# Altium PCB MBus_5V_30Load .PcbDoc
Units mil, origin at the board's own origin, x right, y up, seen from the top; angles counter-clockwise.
Board outline 2910 x 1732.28 mil, 2 copper layers (Top Layer, Bottom Layer); 54 components, 31 nets, 150 pads, 37 vias.
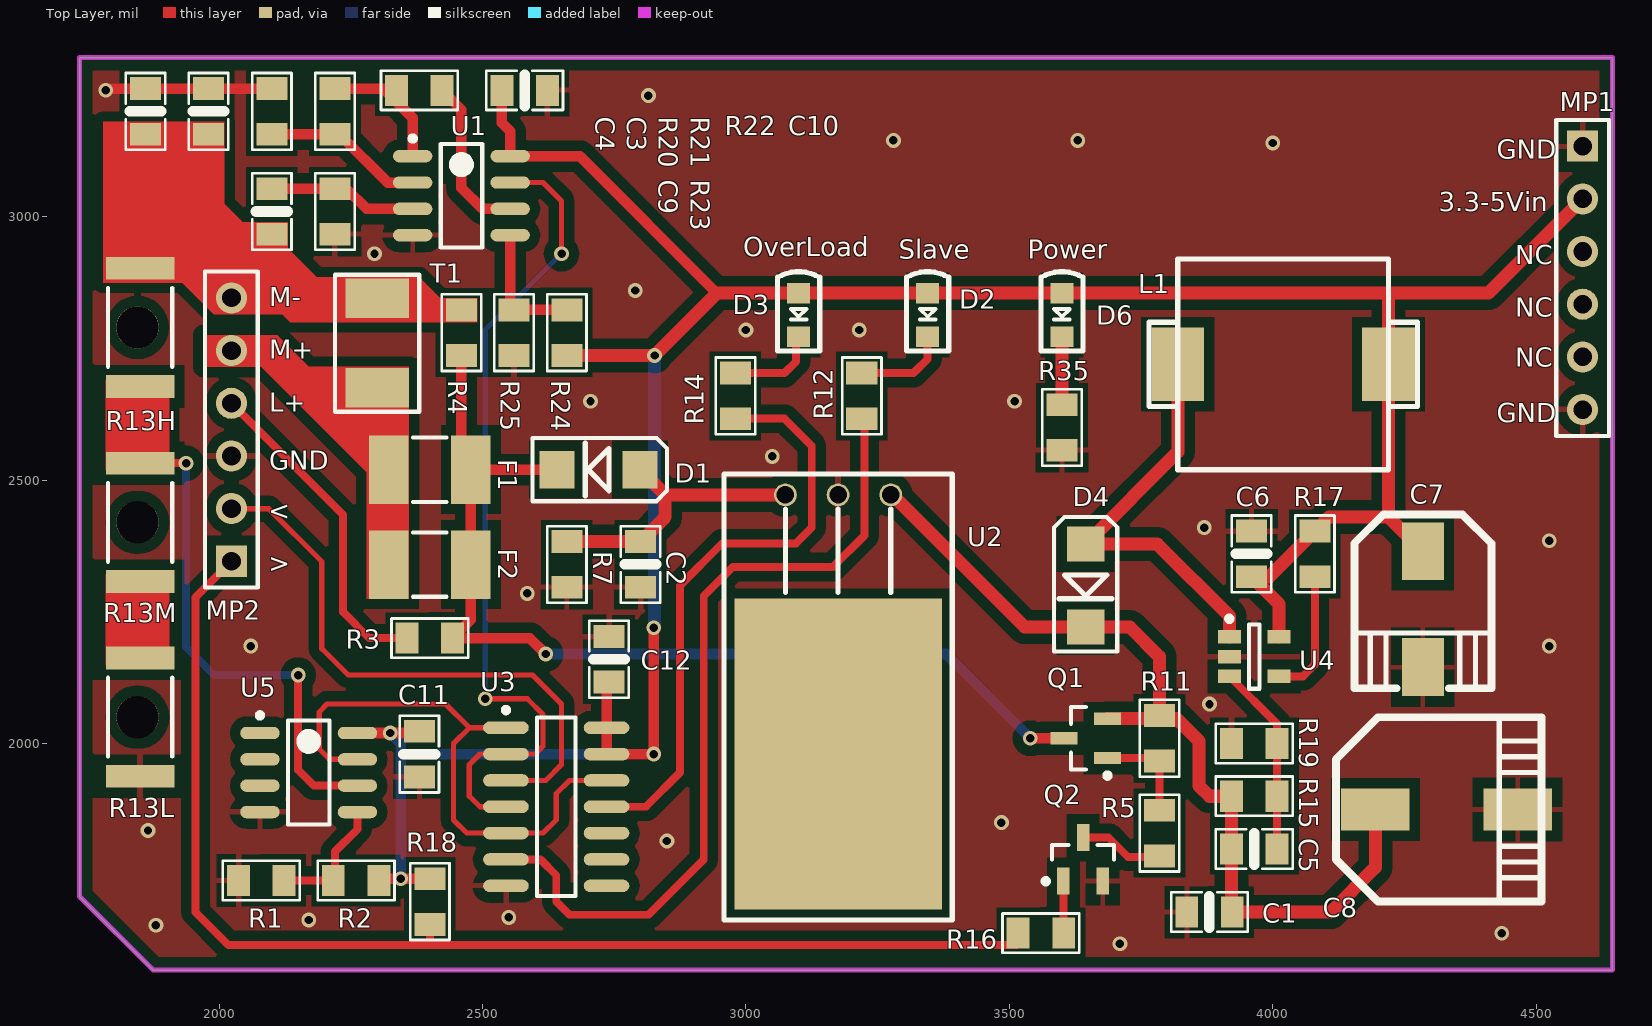
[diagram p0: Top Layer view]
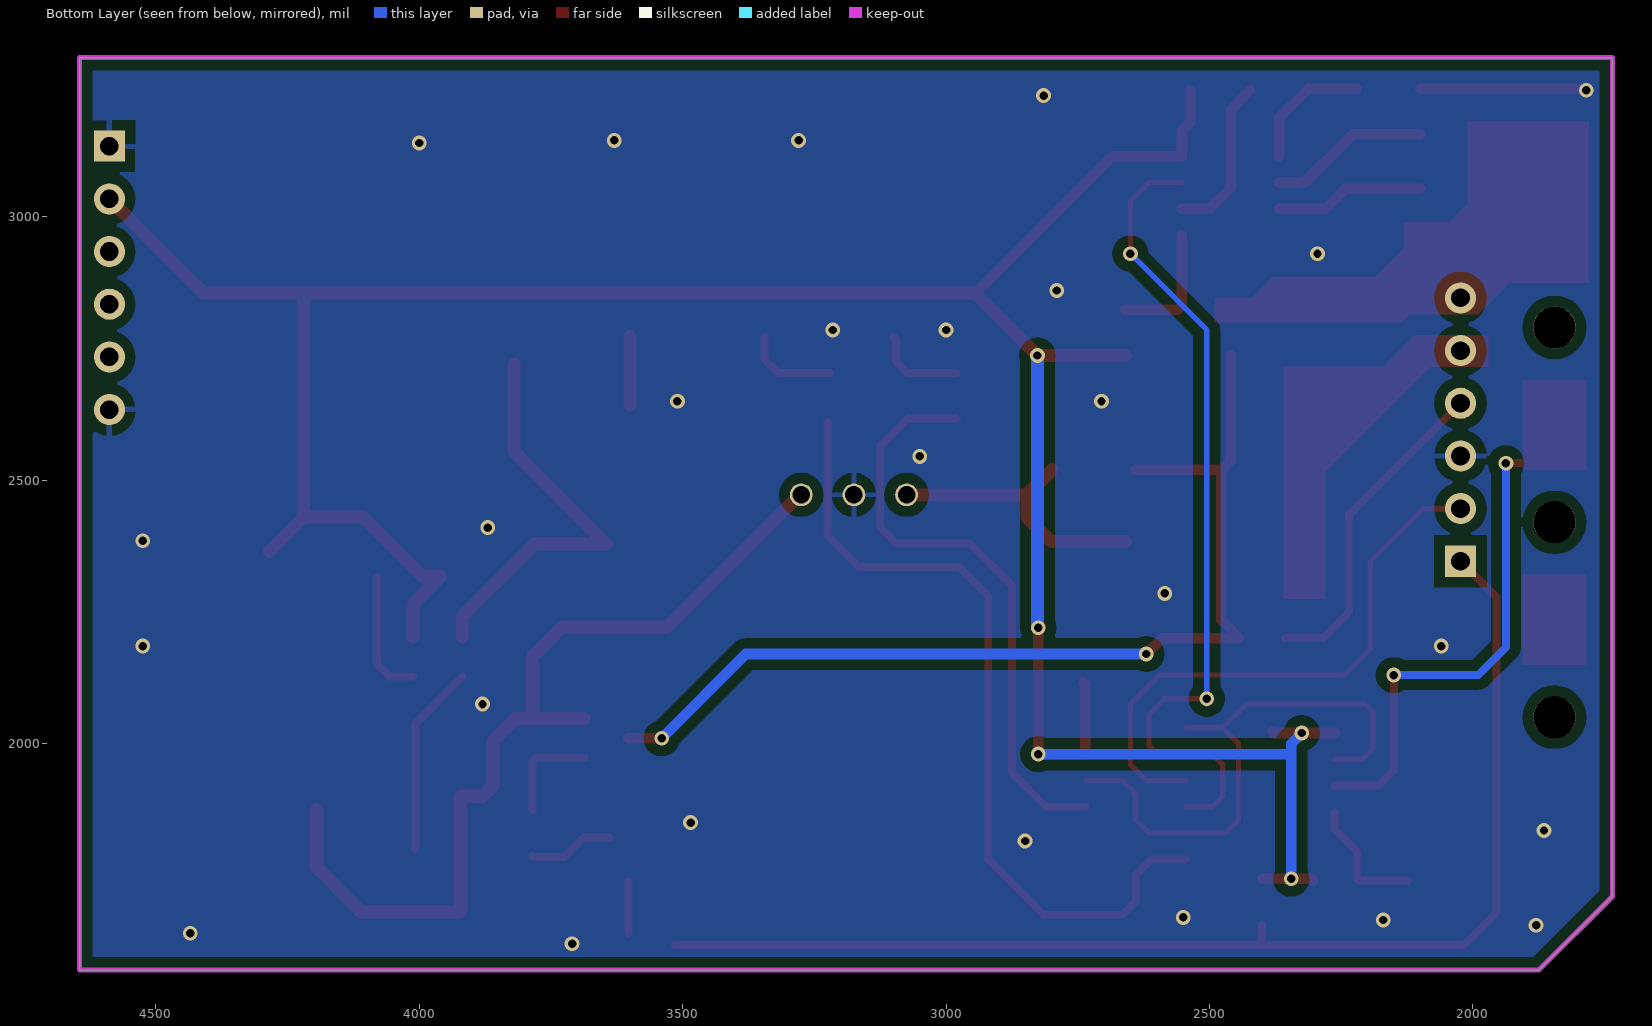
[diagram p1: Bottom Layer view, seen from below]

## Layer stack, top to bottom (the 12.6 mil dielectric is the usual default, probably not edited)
Top Layer: signal copper 1.4
Dielectric: dielectric 12.6, FR-4, Dk 4.8
Bottom Layer: signal copper 1.4

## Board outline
1875,1570 4645,1570 4645,3302.28 1735,3302.28 1735,1710

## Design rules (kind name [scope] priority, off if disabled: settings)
Clearance Clearance_1 [All vs InPolygon] p1: gap=20
Clearance [All] p2: gap=9
MinimumSolderMaskSliver [All] p1: minsoldermaskwidth=0
PlaneClearance [All] p1: clearance=10
PolygonConnect PolygonConnect_1 [IsVia] p1: connectstyle=Direct reliefconductorwidth=10 reliefentries=4 polygonreliefangle="90 Angle"
PolygonConnect [All] p2: connectstyle=Relief reliefconductorwidth=10 reliefentries=4 polygonreliefangle="90 Angle"
RoomDefinition MBus_5V_80Load [InComponentClass('MBus_5V_80Load')] p1: confinementstyle=ConfineIn formatcopy=TRUE lockcomponents=FALSE outline 1085,360 5900,360 5900,3530 1085,3530
RoutingVias [All] p1: holewidth=16 width=28 viastyle="Through Hole" minholewidth=14 minwidth=24 maxholewidth=30 maxwidth=50
SilkToSilkClearance [All] p1: silktosilkclearance=0
SilkscreenOverComponentPads [All] p1: minsilkscreentomaskgap=0
SolderMaskExpansion [All] p1: expansion=4
Width [All] p1: maxlimit=50 minlimit=10 preferedwidth=10 minimp=50.000000 maximp=50.000000 favimp=50.000000
24 further rules are at their usual default settings.

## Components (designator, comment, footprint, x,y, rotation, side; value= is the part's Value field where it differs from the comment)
C1 "0.1uF/50V X7R" 电容器0805 3880,1680 r0 top
C2 "0.1uF/50V X7R" 电容器0805 2800,2340 r90 top
C3 "0.1uF/50V" 电容器0805 1980,3200 r90 top
C4 "1nF/50V" 电容器0805 1860,3200 r90 top
C5 "82pF" 电容器0805 3965,1800 r180 top
C6 "0.1uF/50V" 电容器0805 3960,2360 r90 top
C7 "220uF/16V" 贴片电解电容-8mm 4285,2255 r90 top
C8 "100uF/50V" 贴片电解电容-10mm 4330,1875 r180 top
C9 "10uF/25V" 电容器0805 2100,3010 r270 top
C10 "0.1uF/50V" 电容器0805 2580,3240 r0 top
C11 "0.1uF/50V" 电容器0805 2380,1980 r270 top
C12 "0.1uF/50V" 电容器0805 2740,2160 r90 top
D1 "M7" DO-214AC 2720,2520 r0 top
D2 "MBUS" 0805-LED 3345,2855 r90 top
D3 "OVER" 0805-LED 3100,2855 r90 top
D4 "SS34" DO-214AC 3645,2300 r90 top
D6 "PWR" 0805-LED 3600,2855 r90 top
F1 "自恢复保险丝" PTC1812 2400,2520 r0 top
F2 "自恢复保险丝" PTC1812 2400,2340 r0 top
L1 "33uH" 贴片电感-10mm 4020,2720 r180 top
MP1 "Header 6" HDR1X6 4588.35,3133.98 r270 top locked
MP2 "Header 6" HDR1X6 2023.35,2345.98 r90 top locked
Q1 "FDN5618P" SOT23_N 3645,2010 r180 top
Q2 "S9014" SOT23_N 3640,1780 r90 top
R1 "10K" 电阻器0805 2080,1740 r0 top
R2 "100K(1%)" 电阻器0805 2260,1740 r180 top
R3 "10K" 电阻器0805 2400,2200 r0 top
R4 "270K" 电阻器0805 2460,2780 r90 top
R5 "27K" 电阻器0805 3785,1830 r270 top
R7 "10K" 电阻器0805 2660,2340 r90 top
R11 "10K" 电阻器0805 3785,2010 r90 top
R12 "10K" 电阻器0805 3220,2660 r90 top
R13H "1" RESC6332L 1850,2790 r270 top
R13L "2" RESC6332L 1850,2050 r270 top
R13M "2" RESC6332L 1850,2420 r270 top
R14 "10K" 电阻器0805 2980,2660 r90 top
R15 "285K" 电阻器0805 3965,1900 r180 top
R16 "10K" 电阻器0805 3560,1640 r0 top
R17 "47K" 电阻器0805 4080,2360 r270 top
R18 "100K" 电阻器0805 2400,1700 r90 top
R19 "13K3" 电阻器0805 3965,2000 r0 top
R20 "10K" 电阻器0805 2100,3200 r270 top
R21 "100K(1%)" 电阻器0805 2220,3200 r90 top
R22 "10K" 电阻器0805 2380,3240 r0 top
R23 "270K" 电阻器0805 2220,3010 r270 top
R24 "100K(1%)" 电阻器0805 2660,2780 r90 top
R25 "13K7" 电阻器0805 2560,2780 r90 top
R35 "10K" 电阻器0805 3600,2600 r90 top
T1 "SMBJ43CA" TVS(贴) 2300,2760 r270 top
U1 "LM358D" D008_L 2460,3040 r0 top
U2 "L7818CV" TO-220-3 3175,1980 r180 top
U3 "74HC08" SOP14 2640,1880 r0 top
U4 "LM2733YMF" MF05A_N 3965,2165 r0 top
U5 "LM358D" D008_L 2170,1945 r0 top

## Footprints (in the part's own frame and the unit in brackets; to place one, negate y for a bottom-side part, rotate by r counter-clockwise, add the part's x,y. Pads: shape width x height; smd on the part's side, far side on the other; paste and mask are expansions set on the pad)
0805-LED [mm]
  rect 1x1.1 smd: 1(0,0) 2(-2.1,0)
  silkscreen extent -2.79,-1.02 1.03,1.02
D008_L [mm] "SOIC, 8-Leads, Body 4.9x3.9mm, Pitch 1.27mm, IPC High Density"
  oval 1.9x0.6 smd: 1(-2.35,1.905) 2(-2.35,0.635) 3(-2.35,-0.635) 4(-2.35,-1.905) 5(2.35,-1.905) 6(2.35,-0.635) 7(2.35,0.635) 8(2.35,1.905)
  silkscreen extent -2.47,-2.5 1,2.88, body extent -2,-2.5 2,2.5, height 1.75
DO-214AC [mm]
  rect 1.7x1.8 smd: 1(2,0) 2(-2,0)
  silkscreen extent -3.17,-1.52 3.3,1.52
HDR1X6 [mm] "Connector; Header; 6 Position"
  rect 1.5x1.5 hole 0.9: 1(0,0)
  round 1.5 hole 0.9: 2(2.54,0) 3(5.08,0) 4(7.62,0) 5(10.16,0) 6(12.7,0)
  silkscreen extent -1.27,-1.27 13.97,1.27
MF05A_N [mm] "SOT23, 5-Leads, Body 2.9x1.6mm, Pitch 0.95mm, Lead Span 2.8mm, IPC Medium Density"
  rect 1.1x0.65 smd: 1(-1.2,0.95) 2(-1.2,0) 3(-1.2,-0.95) 4(1.2,-0.95) 5(1.2,0.95)
  silkscreen extent -1.32,-1.55 0.25,1.95, body extent -0.9,-1.55 0.9,1.55, height 1.19
PTC1812 [mm]
  rect 1.905x3.3 smd: 1(1.981,-0.005)
  rect 1.908x3.3 smd: 2(-1.981,-0.005)
  silkscreen extent -0.81,-1.56 0.79,1.55, body extent -2.41,-1.71 2.39,1.69, height 1.4
RESC6332L [mm] "Chip Resistor, Body 6.3x3.2mm, IPC High Density"
  rect 1.1x3.3 smd: 1(-2.85,0) 2(2.85,0)
  silkscreen extent -1.9,-1.55 1.9,1.55, body extent -3.22,-1.68 3.22,1.68, height 0.9
SOP14 [mm] "74HCxx"
  oval 2.2x0.6 smd: 1(-2.425,3.81) 2(-2.425,2.54) 3(-2.425,1.27) 4(-2.425,0) 5(-2.425,-1.27) 6(-2.425,-2.54) 7(-2.425,-3.81) 8(2.425,-3.81) 9(2.425,-2.54) 10(2.425,-1.27) 11(2.425,0) 12(2.425,1.27) 13(2.425,2.54) 14(2.425,3.81)
  silkscreen extent -2.55,-4.3 0.93,4.78, body extent -2,-4.28 2,4.28, height 1.75
SOT23_N [mm] "SOT23, 3-Leads, Body 2.9x1.3mm, Pitch 0.95mm, Lead Span 2.3mm, IPC Medium Density"
  rect 1.3x0.6 smd: 1(-1.05,0.95) 2(-1.05,-0.95) 3(1.05,0)
  silkscreen extent -1.18,-1.5 0.7,1.92, body extent -0.7,-1.5 0.7,1.5, height 1.1
TO-220-3 [mm]
  round 1.1 hole 0.85: 1(-2.54,-12.5) 2(0,-12.5) 3(2.54,-12.5)
  rect 10x15 smd: ""(0,0)
  silkscreen extent -5.5,-13.5 5.5,8
TVS(贴) [mil]
  rect 75x120 smd: 1(-85,0) 2(85,0)
  silkscreen extent -130,-80 130,80
电容器0805 [mm]
  rect 1.1x1.5 smd: 1(-1.1,0) 2(1.1,0)
  silkscreen extent -1.85,-0.95 1.85,0.95
电阻器0805 [mm]
  rect 1.1x1.5 smd: 1(-1.1,0) 2(1.1,0)
  silkscreen extent -1.85,-0.95 1.85,0.95
贴片电感-10mm [mil]
  rect 100x140 smd: 1(-200,0) 2(200,0)
  silkscreen extent -255,-200 255,200
贴片电解电容-8mm [mil]
  rect 110x80 smd: 1(110,0) 2(-110,0)
  silkscreen extent -150,-130 180,130
贴片电解电容-10mm [mil]
  rect 130x80 smd: 1(135,0) 2(-135,0)
  silkscreen extent -180,-175 210,175

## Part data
C1 C2 C3 C4 C5 C9: library part Cap, "Capacitor"
C6 C10 C11 C12: library part CAP2, "Capacitor"
C7 C8: library part "Cap Pol1", "Polarized Capacitor (Radial)"
D1: library part "Diode 1N4007", "High Conductance Fast Diode"
D2 D3 D6: library part LED2, "Typical RED, GREEN, YELLOW, AMBER GaAs LED"
D4: library part "D Schottky", "Schottky Diode"
F1 F2: library part "Fuse 1", "Fuse"
L1: library part "Inductor Iron", "Magnetic-Core Inductor"
MP1 MP2: "Header, 6-Pin"
Q1: library part MOSFET-P, "P-Channel MOSFET"
Q2: library part NPN, "NPN Bipolar Transistor"
R1 R2 R3 R4 R5 R7 R11 R12 R13H R13L R13M R14 R15 R16 R17 R18 R19 R20 R21 R22 R23 R24 R25 R35: library part Res1, "Resistor"
T1: library part "D Zener", "Zener Diode"
U1 U5: "Dual Low-Power Operational Amplifier"
U2: library part L7815ABV, "Precision 1A Regulator"
U3: library part 74LS08, "与门"
U4: "0.6/1.6 MHz Boost Converters With 40V Internal FET Switch in SOT-23"

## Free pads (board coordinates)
  round 80 hole 80: 0(1845,2050) 0(1845,2420) 0(1845,2790)

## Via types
v1: diameter 28, hole 16, Top Layer to Bottom Layer, 37 vias

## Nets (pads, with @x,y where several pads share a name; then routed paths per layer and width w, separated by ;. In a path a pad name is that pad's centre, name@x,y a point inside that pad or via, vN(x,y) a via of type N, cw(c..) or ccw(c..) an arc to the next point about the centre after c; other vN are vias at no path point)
+5V: C6.1 C7.1 C10.1 C11.1 C12.1 D2.1 D3.1 D6.1 L1.1 MP1.2 R2.1 R17.1 R18.2 R24.1 U1.8 U3.13 U3.14 U4.5 U5.8 | length 5610.4
  Top Layer w20: U5.8 v1(2325,2020) 2376.69,2020 C11.1 ; R2.1 2306.61,1743.31 v1(2345,1743.31) R18.2 ; C10.1 2536.69,3178.31 2552.52,3162.48 U1.8 2685,3115 2945,2855 ; C12.1 2735.47,2112.17 U3.14 U3.13 v1(2825,1980) v1(2825,2220)
  Top Layer w25: R24.1 v1(2826.69,2736.69) 2945,2855 D3.1 D2.1 4220,2855 ; U4.5 4012.24,2264.45 C6.1 3993.39,2316.69 R17.1 4106.69,2430 4220,2430 ; C7.1 4220,2430 ; MP1.2 4409.37,2855 4220,2855 ; 4220,2430 L1.1 4220,2855
  Bottom Layer w20: v1(2325,2020) 2345,2000 2345,1980 ; v1(2345,1743.31) 2345,1980 ; v1(2825,1980) 2345,1980
  Bottom Layer w25: v1(2825,2220) 2826.69,2221.69 v1(2826.69,2736.69)
+18V: C2.2 D1.1 R7.2 U2.3 | length 544.2
  Top Layer w25: R7.2 C2.2 2846.61,2429.92 2846.61,2472.13 ; D1.1 2846.61,2472.13 ; U2.3 2846.61,2472.13
+28V: C1.2 C5.2 C8.1 D4.2 Q1.2 R11.2 R15.2 U2.1 | length 1741
  Top Layer w25: U2.1 3278.08,2472.13 3528.94,2221.26 D4.2 3728.74,2221.26 3785,2165 R11.2 R11.2@3779.09,2047.4 ; Q1.2 R11.2@3779.09,2047.4 ; C8.1 4195,1765 4110,1680 C1.2 3921.69,1681.61 C5.2 R15.2 3880,1900 3860,1920 3860,2005 3817.6,2047.4 R11.2@3779.09,2047.4
GND: C1.1 C2.1 C3.2 C4.2 C6.2 C7.2 C8.2 C10.2 C11.2 C12.2 MP1.1 MP1.6 MP2.3 Q2.2 R1.1 R7.1 R13L.2 R19.1 R20.1 R23.2 R25.1 R35.1 U1.4 U2.2 U3.7 U4.2 U5.4 | length 316.4
  Top Layer w20: v1(1785,3240) 1788.31,3243.31 C4.2 C3.2 R20.1
  other v1: 3710,1620 4435,1640 1880,1655 2170,1665 2550,1670 2850,1815 1865,1835 3485,1850 3880,2075 2060,2185 4525,2185 2585,2285 4525,2385 3870,2410 3050,2545 2705,2650 3510,2650 3000,2785 3215,2785 2790,2860 2295,2930 4000,3140 3280,3145 3630,3145 2815,3230
L+: MP2.4 R3.1 | length 626
  Top Layer w15: MP2.4 2235,2434.32 2235,2250 2285,2200 R3.1
M+: F1.2 F2.2 MP2.5 T1.2
M-: C3.1 C4.1 C9.2 MP2.6 R4.2 R13H.1 T1.1
NetC5_1: C5.1 R15.1 R19.2 U4.3 | length 365.1
  Top Layer w15: U4.3 4008.31,2037.05 R19.2 R15.1 C5.1
NetC9_1: C9.1 R23.1 U1.3 | length 283.3
  Top Layer w20: C9.1 R23.1 2241.69,3053.31 2280,3015 U1.3
NetD1_2: D1.2 F1.1 F2.1 Q1.3 R3.2 R4.1 | length 1960.8
  Top Layer w20: R4.1 2460,2537.8 2477.8,2520 D1.2 ; F1.1 F2.1 2478,2234.69 R3.2 2590,2200 v1(2620,2170) ; v1(3540,2010) Q1.3
  Bottom Layer w20: v1(2620,2170) 3380,2170 v1(3540,2010)
NetD2_2: D2.2 R12.2 | length 178.4
  Top Layer w15: R12.2 3318.31,2703.31 3345,2730 D2.2
NetD3_2: D3.2 R14.2 | length 173.4
  Top Layer w15: R14.2 3073.31,2703.31 3095,2725 3095,2767.32 D3.2
NetD4_1: D4.1 L1.2 U4.1 | length 782.9
  Top Layer w25: L1.2 3820,2553.74 D4.1 3781.26,2378.74 3917.76,2242.24 U4.1
NetD6_2: D6.2 R35.2 | length 129
  Top Layer w25: R35.2 D6.2
NetQ1_2: Q1.1 R5.1 R11.1 | length 194.5
  Top Layer w15: Q1.1 3779.09,1972.6 R11.1 R5.1
NetQ2_1: Q2.3 R5.2 | length 160.8
  Top Layer w15: Q2.3 3688.66,1821.34 3725,1785 3783.31,1785 R5.2
NetQ2_2: Q2.1 R16.2 | length 99
  Top Layer w15: Q2.1 3602.6,1640.71 R16.2
NetR1_2: R1.2 R2.2 U5.5 | length 242.4
  Top Layer w15: R1.2 R2.2 2220,1743.31 2220,1795 2262.52,1837.52 U5.5
NetR12_1: R12.1 U3.6 | length 1559.4
  Top Layer w15: U3.6 2610,1780 2640,1750 2640,1700 2665,1675 2815,1675 2920,1780 2920,2280 2975,2335 3165,2335 3225,2395 R12.1@3225,2610
NetR13H_2: R13H.2 R13M.1 U5.6 | length 976.2
  Top Layer w15: R13M.1 v1(1937.2,2532.2) ; v1(2150,2130) 2150,1950 2180,1920 U5.6
  Bottom Layer w15: v1(1937.2,2532.2) 1937.2,2182.8 1990,2130 v1(2150,2130)
NetR13L_1: R13L.1 R13M.2
NetR14_1: R14.1 U3.11 | length 1138.4
  Top Layer w15: U3.11 2810,1880 2875,1945 2875,2300 2955,2380 3095,2380 3125,2410 3125,2565 3073.31,2616.69 R14.1
NetR17_2: R17.2 U4.4 | length 243.7
  Top Layer w15: U4.4 4057.6,2127.6 4080,2150 R17.2
NetR20_2: R20.2 R21.1 U1.2 | length 305.5
  Top Layer w20: R20.2 R21.1 2228.31,3156.69 2320,3065 U1.2
NetR21_2: R21.2 R22.1 U1.1 | length 243.1
  Top Layer w20: R21.2 2311.69,3243.31 2367.48,3187.52 U1.1
NetR22_2: R22.2 U1.6 | length 309.3
  Top Layer w20: R22.2 2460,3203.31 2460,3055 2500,3015 U1.6
NetR24_2: R24.2 R25.2 U1.5 | length 244.8
  Top Layer w20: U1.5 2552.52,2830.79 R25.2 R24.2
NetU1_7: U1.7 U3.2 U3.4 | length 1601.8
  Top Layer w10: v1(2505,2085) 2585,2085 2615,2055 2615,1995 2600,1980 U3.2 2495,1980 2475,1960 2475,1900 2495,1880 U3.4 ; U1.7 2615,3065 2650,3030 v1(2650,2930)
  Bottom Layer w10: v1@2505,2075 v1(2505,2085) 2505,2785 v1(2650,2930)
OVERLOAD: U3.1 U3.5 U3.12 U5.7 | length 1089.1
  Top Layer w10: U5.7 2210,1970 2190,1990 2190,2060 2205,2075 2430,2075 2475,2030 ; U3.1 2475,2030 ; U3.12 2665,1930 2640,1905 2640,1855 2615,1830 U3.5 2470,1830 2445,1855 2445,2000 2475,2030
RX: MP2.1 R16.1 R18.1 | length 2319.3
  Top Layer w15: MP2.1 1955,2277.63 1955,1680 2017.46,1617.54 2400,1617.54 ; R18.1 2400,1617.54 ; R16.1@3515,1617.54 2400,1617.54
TX: MP2.2 U3.3 | length 1109.9
  Top Layer w10: MP2.2 2094.02,2445.98 2195,2345 2195,2180 2245,2130 2595,2130 2650,2075 2650,1960 2620,1930 U3.3
pads on no net: MP1.3 MP1.4 MP1.5 U2. U3.8 U3.9 U3.10 U5.1 U5.2 U5.3

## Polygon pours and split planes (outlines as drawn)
GND on Top Layer "Bottom Layer-No Net" (solid, pour order 1000): 1875,1570 4645,1570 4645,3302.28 1735,3302.28 1735,1710
GND on Bottom Layer "Bottom Layer-No Net" (solid, pour order 1001): 1875,1570 4645,1570 4645,3302.28 1735,3302.28 1735,1710

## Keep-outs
Keep-Out Layer:
  the board outline again, w10

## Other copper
Top Layer:
  region net NetR13H_2: 1905,2690 1905,2520 1785,2520 1785,2690
  region net NetR13L_1: 1905,2320 1905,2150 1785,2150 1785,2320
  region net M-: 2490,2800 2135,2800 2120,2815 1990,2815 1930,2875 1780,2875 1780,3180 2010,3180 2010,3025 2045,2990 2130,2990 2130,2940 2185,2885 2380,2885 2420,2845 2490,2845
  region net M+: 2360,2275 2360,2715 2170,2715 2110,2775 1970,2775 1970,2715 2080,2715 2280,2515 2280,2275

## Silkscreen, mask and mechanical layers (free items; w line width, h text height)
Top Overlay:
  text "GND" at 4425,3110 h36
  text "3.3-5Vin" at 4315,3010 h36
  text "OverLoad" at 2995,2925 h36
  text "Slave" at 3290,2920 h36
  text "Power" at 3535,2920 h36
  text "NC" at 4460,2910 h36
  text "M-" at 2095,2830 h36
  text "NC" at 4460,2810 h36
  text "M+" at 2095,2730 h36
  text "NC" at 4460,2715 h36
  text "L+" at 2095,2630 h36
  text "GND" at 4425,2610 h36
  text "GND" at 2095,2520 h36
  text ">" at 2135,2425 h36
  text "<" at 2135,2325 h36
